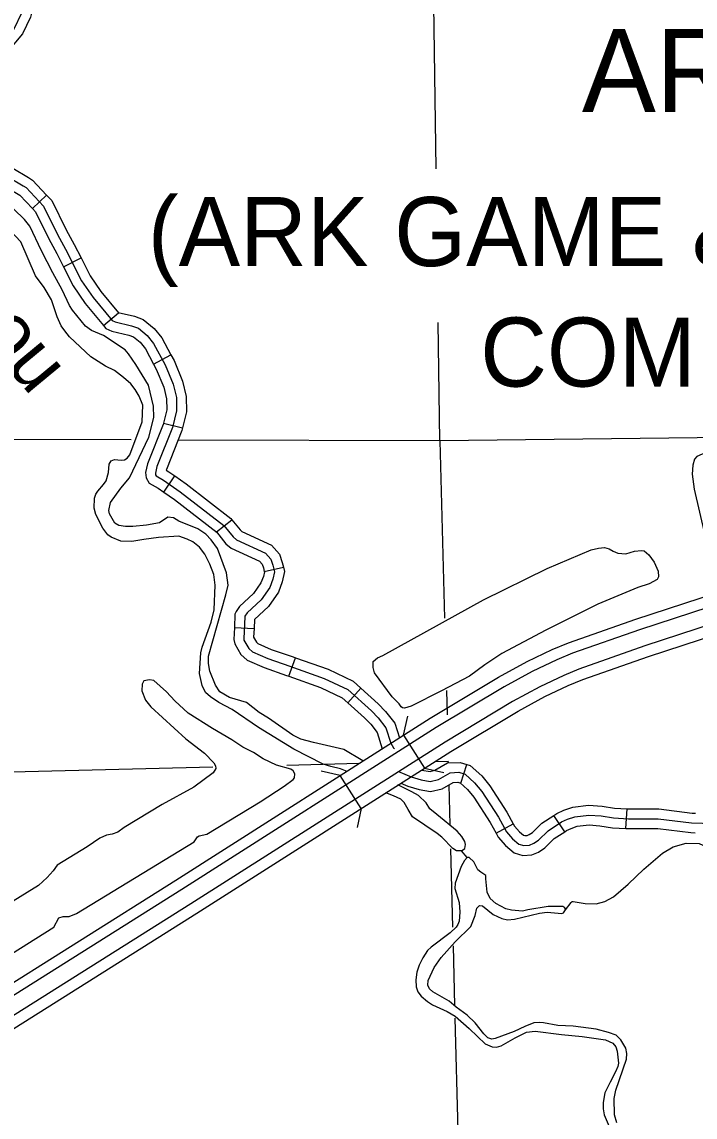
# Model space of a CAD drawing. Extents: x 1084508 to 1142749, y 1057638 to 1093403.
# Drawn here: x 1090132 to 1091747, y 1070432 to 1073059 of the extents above; entities that cross this region are included whole.
import ezdxf

# ---------------------------------------------------------------- set-up
doc = ezdxf.new("R2010")
doc.units = 0
for name, color, linetype in [('Level 19', 7, 'Continuous'), ('Level 32', 7, 'Continuous'), ('Level 35', 7, 'Continuous'), ('Level 39', 7, 'Continuous'), ('Level 5', 7, 'Continuous'), ('Level 7', 7, 'Continuous')]:
    doc.layers.add(name, color=color, linetype=linetype)

msp = doc.modelspace()

# ---------------------------------------------------------------- linework, layer by layer
at = {"layer": 'Level 19'}
for points in [[(1086828.8, 1069564.8), (1086958.3, 1069597.9), (1087305.2, 1069683.8), (1087445.9, 1069710.7), (1087821, 1069773.1), (1088253.5, 1069840.9), (1088436.6, 1069876.1), (1088626, 1069927.2), (1088752.5, 1069969), (1088851.8, 1070006.5), (1088959.6, 1070052.9), (1089051.3, 1070099.1), (1089145.7, 1070149.3), (1089264, 1070224), (1089345.2, 1070271.9), (1090501.3, 1071000.2), (1091111.9, 1071388.7), (1091276, 1071487.3), (1091344.3, 1071524.2), (1091404.7, 1071552.9), (1091443.8, 1071569.2), (1091605.2, 1071625.7), (1092224.5, 1071828.5), (1094022, 1072425.4)], [(1094030.9, 1072400.2), (1092232.9, 1071803.1), (1091613.8, 1071600.4), (1091453.4, 1071544.3), (1091415.6, 1071528.5), (1091356.3, 1071500.4), (1091289.2, 1071464.1), (1091126, 1071366), (1090515.6, 1070977.7), (1089359.1, 1070249.2), (1089277.9, 1070201.2), (1089159.1, 1070126.2), (1089063.6, 1070075.4), (1088970.9, 1070028.7), (1088861.8, 1069981.8), (1088761.4, 1069943.9), (1088633.7, 1069901.6), (1088442.6, 1069850.1), (1088258.1, 1069814.7), (1087825.3, 1069746.7), (1087450.6, 1069684.4), (1087310.9, 1069657.7), (1086964.9, 1069572), (1086833.1, 1069538.3)], [(1094044.5, 1072361.7), (1092245.7, 1071764.4), (1091626.8, 1071561.8), (1091468, 1071506.2), (1091432.2, 1071491.3), (1091374.8, 1071464), (1091309.5, 1071428.7), (1091147.4, 1071331.3), (1090537.4, 1070943.2), (1089380.4, 1070214.3), (1089299.2, 1070166.4), (1089179.6, 1070090.9), (1089082.3, 1070039.1), (1088988.1, 1069991.7), (1088877.1, 1069943.9), (1088775, 1069905.4), (1088645.4, 1069862.5), (1088451.8, 1069810.3), (1088265.1, 1069774.4), (1087831.8, 1069706.5), (1087457.7, 1069644.3), (1087319.6, 1069617.8), (1086974.8, 1069532.5), (1086844.1, 1069499)], [(1086853, 1069473.8), (1086981.3, 1069506.6), (1087325.3, 1069591.8), (1087462.4, 1069618), (1087836, 1069680.1), (1088269.7, 1069748.2), (1088457.8, 1069784.3), (1088653.1, 1069837), (1088783.9, 1069880.3), (1088887.1, 1069919.2), (1088999.4, 1069967.5), (1089094.6, 1070015.5), (1089193, 1070067.8), (1089313.1, 1070143.6), (1089394.3, 1070191.5), (1090551.7, 1070920.7), (1091161.5, 1071308.6), (1091322.7, 1071405.5), (1091386.9, 1071440.2), (1091443.1, 1071466.9), (1091477.6, 1071481.3), (1091635.4, 1071536.5), (1092254, 1071739), (1094053.4, 1072336.6)]]:
    msp.add_lwpolyline(points, dxfattribs=at)
at = {"layer": 'Level 32'}
for p, q in [((1090157.5, 1072611), (1090191.7, 1072643.4)), ((1090232.2, 1072471.4), (1090274.3, 1072492.5)), ((1090328.1, 1072330.6), (1090364.3, 1072360.6)), ((1090448.3, 1072237.8), (1090489.9, 1072260)), ((1090471.9, 1072096.2), (1090517.6, 1072085.1)), ((1090472.6, 1071930.9), (1090499.4, 1071969.5)), ((1090599.5, 1071835.2), (1090636.3, 1071864.6)), ((1090713.7, 1071740.1), (1090759.5, 1071751.1)), ((1090642.1, 1071605.7), (1090689.1, 1071603.6)), ((1090772.5, 1071489.2), (1090788.3, 1071533.6)), ((1090914.1, 1071425.5), (1090945.6, 1071460.5)), ((1091185.2, 1071232.8), (1091199.3, 1071277.7)), ((1091581.3, 1071123.9), (1091584, 1071171)), ((1091434.4, 1071116.2), (1091408.1, 1071155.3)), ((1091269.8, 1071112.5), (1091311, 1071135.2))]:
    msp.add_line(p, q, dxfattribs=at)
for points in [[(1090156.6, 1073133.5), (1090159.5, 1073121.6), (1090160.4, 1073098.9), (1090152.9, 1073069.9), (1090134, 1073030.3), (1090096.4, 1072985.1), (1090086.4, 1072970.3)], [(1090130.7, 1073078), (1090114, 1073043.1), (1090077.6, 1072999.3), (1090062.9, 1072977.5), (1090050.2, 1072964.1), (1089963, 1072900), (1089959.3, 1072895.6), (1089958.6, 1072893.5), (1089959.2, 1072889.9), (1090031.9, 1072734.5), (1090045.1, 1072720.5), (1090059.2, 1072710.5), (1090135.7, 1072665.8)], [(1090058.9, 1072740.2), (1090060.6, 1072738.4), (1090072, 1072730.4), (1090148.4, 1072685.7), (1090157.8, 1072679.2), (1090191.7, 1072643.4)], [(1090024.7, 1072707.9), (1090029.6, 1072702.6), (1090046.5, 1072690.7), (1090123.1, 1072646), (1090127, 1072643.3), (1090157.5, 1072611)], [(1090135.7, 1072665.8), (1090142.4, 1072661.3), (1090184.4, 1072616.9), (1090218, 1072549.1), (1090237.2, 1072514), (1090275.4, 1072437.7), (1090303.1, 1072397.7), (1090348.6, 1072342.6), (1090355.7, 1072339.4), (1090395.5, 1072330), (1090411.7, 1072324.2), (1090432.9, 1072306.9), (1090448.4, 1072287.7), (1090475.9, 1072236.1), (1090495.4, 1072189.9), (1090502.8, 1072157.8), (1090503.3, 1072125.9), (1090493.6, 1072085.8), (1090456.2, 1071992.2), (1090452.9, 1071976.3), (1090453.2, 1071972.6), (1090454.8, 1071970), (1090472.1, 1071959.8), (1090512.3, 1071931.9), (1090617.1, 1071850.8), (1090638.8, 1071823.6), (1090647.2, 1071816.6), (1090716.8, 1071784.5), (1090729.2, 1071769.9), (1090734.2, 1071755.6)], [(1090191.7, 1072643.4), (1090203.9, 1072630.5), (1090238.9, 1072560), (1090258.1, 1072524.9), (1090274.3, 1072492.5)], [(1090157.5, 1072611), (1090164.9, 1072603.3), (1090197.2, 1072538.2), (1090216.4, 1072503.1), (1090232.2, 1072471.4)], [(1090274.3, 1072492.5), (1090295.7, 1072449.7), (1090321.9, 1072411.9), (1090364.3, 1072360.6)], [(1090232.2, 1072471.4), (1090255.1, 1072425.7), (1090284.3, 1072383.4), (1090328.1, 1072330.6)], [(1090363.3, 1072361.8), (1090363.3, 1072361.8), (1090402.2, 1072352.6), (1090423.4, 1072345), (1090449.7, 1072323.5), (1090468.1, 1072300.7), (1090489.9, 1072260)], [(1090328.1, 1072330.6), (1090334, 1072323.4), (1090348, 1072317.1), (1090388.8, 1072307.3), (1090399.9, 1072303.4), (1090416.1, 1072290.2), (1090428.6, 1072274.6), (1090448.3, 1072237.8)], [(1090489.9, 1072260), (1090497.2, 1072246.3), (1090517.9, 1072197.2), (1090526.3, 1072160.6), (1090526.9, 1072123.2), (1090517.6, 1072085.1)], [(1090448.3, 1072237.8), (1090454.7, 1072226), (1090472.9, 1072182.7), (1090479.3, 1072154.9), (1090479.7, 1072128.5), (1090471.9, 1072096.2)], [(1090471.9, 1072096.2), (1090471.1, 1072093), (1090433.6, 1071999), (1090429.1, 1071977.8), (1090430.3, 1071964.9), (1090437.9, 1071952.7), (1090459.4, 1071940), (1090472.6, 1071930.9)], [(1090517.6, 1072085.1), (1090516, 1072078.6), (1090478.9, 1071985.3), (1090478.5, 1071983.4), (1090484.9, 1071979.7), (1090499.4, 1071969.5)], [(1090499.4, 1071969.5), (1090526.3, 1071950.9), (1090633.8, 1071867.7), (1090636.3, 1071864.6)], [(1090472.6, 1071930.9), (1090498.4, 1071912.9), (1090600.5, 1071833.9), (1090599.4, 1071835.2)], [(1090636.3, 1071864.6), (1090655.7, 1071840.2), (1090659.9, 1071836.7), (1090731.3, 1071803.7), (1090749.9, 1071781.9), (1090756.8, 1071762.3), (1090759.5, 1071751.1)], [(1090599.5, 1071835.2), (1090621.9, 1071807.1), (1090634.6, 1071796.6), (1090702.2, 1071765.2), (1090708.5, 1071757.9), (1090711.6, 1071748.9), (1090713.7, 1071740.1)], [(1090734.2, 1071755.6), (1090738, 1071739.9), (1090734.1, 1071721.9), (1090726.8, 1071702.2), (1090705.9, 1071672.2), (1090672.6, 1071641), (1090666.9, 1071632.9), (1090666.8, 1071632.7), (1090664.5, 1071578.8), (1090665.1, 1071575.4), (1090676.4, 1071555.9), (1090685.7, 1071547.7), (1090722, 1071531.6), (1090775.1, 1071513.3), (1090857.7, 1071484), (1090913.9, 1071457.3), (1090970.8, 1071406.2), (1090986.8, 1071389.3), (1091005.7, 1071365.5), (1091017.3, 1071328.2), (1091023.7, 1071317.4), (1091025.9, 1071315.5)], [(1090759.5, 1071751.1), (1090762.1, 1071740.2), (1090756.8, 1071715.3), (1090747.8, 1071691.2), (1090723.8, 1071656.7), (1090690.4, 1071625.4), (1090690.1, 1071624.9), (1090689.1, 1071603.6)], [(1090713.7, 1071740.1), (1090713.9, 1071739.6), (1090711.5, 1071728.5), (1090705.8, 1071713.2), (1090688, 1071687.6), (1090654.7, 1071656.5), (1090646.1, 1071644.2), (1090643.5, 1071637.8), (1090642.1, 1071605.7)], [(1090642.1, 1071605.7), (1090640.8, 1071577), (1090642.8, 1071567), (1090657.9, 1071540.9), (1090672.8, 1071527.6), (1090713.3, 1071509.7), (1090767.3, 1071491.1), (1090772.5, 1071489.2)], [(1090689.1, 1071603.6), (1090688.2, 1071582.5), (1090694.8, 1071571), (1090698.6, 1071567.7), (1090730.6, 1071553.6), (1090782.9, 1071535.5), (1090788.3, 1071533.6)], [(1090788.3, 1071533.6), (1090866.7, 1071505.8), (1090927.1, 1071477.1), (1090945.6, 1071460.5)], [(1090772.5, 1071489.2), (1090848.7, 1071462.2), (1090900.8, 1071437.5), (1090914.1, 1071425.5)], [(1090945.6, 1071460.5), (1090987.2, 1071423.1), (1091004.6, 1071404.8), (1091026.9, 1071376.7), (1091037.8, 1071341.5)], [(1090914.1, 1071425.5), (1090954.3, 1071389.3), (1090969, 1071373.8), (1090984.5, 1071354.3), (1090996.6, 1071315.3)], [(1091091.7, 1071264.2), (1091111.3, 1071260.9), (1091122.9, 1071263.5), (1091152.9, 1071281), (1091183.8, 1071282.5), (1091199.3, 1071277.7)], [(1091199.3, 1071277.7), (1091207.6, 1071275.1), (1091235.3, 1071250.1), (1091254.5, 1071226.5), (1091295.8, 1071162.8), (1091311, 1071135.2)], [(1091035.9, 1071260.3), (1091065.8, 1071247.5), (1091090.2, 1071240.6), (1091112, 1071237), (1091131.6, 1071241.3), (1091159.8, 1071257.8), (1091180.8, 1071258.8), (1091195.7, 1071254.2), (1091218.2, 1071233.8), (1091235.4, 1071212.6)], [(1091041.6, 1071232.3), (1091058, 1071225.2), (1091085.1, 1071217.6), (1091112.6, 1071213), (1091140.3, 1071219.2), (1091166.7, 1071234.6), (1091177.7, 1071235.1), (1091185.2, 1071232.8)], [(1091183.7, 1071233.2), (1091201, 1071217.6), (1091216.4, 1071198.7), (1091255.4, 1071138.5), (1091269.8, 1071112.5)], [(1091235.4, 1071212.6), (1091275.6, 1071150.7), (1091294.6, 1071116.2), (1091309.1, 1071099.4), (1091324.3, 1071086.5), (1091336.7, 1071082.9), (1091349.8, 1071084.1), (1091360.3, 1071088.3), (1091371.6, 1071095.9), (1091394.6, 1071117.9), (1091427, 1071139.6), (1091440.8, 1071146.1), (1091459.1, 1071152.2), (1091492.2, 1071156), (1091521.7, 1071154), (1091551.7, 1071149.2), (1091587.5, 1071147.2), (1091659, 1071147.1), (1091738.6, 1071137.4), (1091816.8, 1071135.4), (1091868.3, 1071131.8), (1091930.3, 1071133.6)], [(1091408.1, 1071155.3), (1091415.3, 1071160.2), (1091432.1, 1071168), (1091454, 1071175.3), (1091491.6, 1071179.6), (1091524.4, 1071177.4), (1091554.2, 1071172.7), (1091584, 1071171)], [(1091584, 1071171), (1091588.2, 1071170.7), (1091660.4, 1071170.7), (1091740.4, 1071160.9), (1091748.4, 1071160.7)], [(1091311, 1071135.2), (1091314.1, 1071129.7), (1091325.7, 1071116.2), (1091335.7, 1071107.7), (1091339, 1071106.8), (1091344.3, 1071107.2), (1091349.2, 1071109.2), (1091356.8, 1071114.3), (1091379.8, 1071136.3), (1091408.1, 1071155.3)], [(1091269.8, 1071112.5), (1091275.2, 1071102.7), (1091292.5, 1071082.7), (1091312.9, 1071065.3), (1091334.3, 1071059.1), (1091355.3, 1071060.9), (1091371.4, 1071067.3), (1091386.5, 1071077.6), (1091409.4, 1071099.5), (1091434.4, 1071116.2)], [(1091434.4, 1071116.2), (1091438.6, 1071119.1), (1091449.6, 1071124.2), (1091464.2, 1071129.1), (1091492.7, 1071132.4), (1091519, 1071130.6), (1091549.1, 1071125.8), (1091581.3, 1071123.9)], [(1091581.3, 1071123.9), (1091586.8, 1071123.6), (1091657.5, 1071123.6), (1091736.9, 1071113.9), (1091747.2, 1071113.6)]]:
    msp.add_lwpolyline(points, dxfattribs=at)
at = {"layer": 'Level 35'}
for points in [[(1090354.4, 1072222.6), (1090333, 1072232.9), (1090297.5, 1072255.3), (1090246.8, 1072303.6), (1090235.1, 1072317.4), (1090226.8, 1072329.7), (1090216.7, 1072351.1), (1090203.5, 1072391.8), (1090186, 1072421.4), (1090165, 1072449.7), (1090129.5, 1072531.2), (1090090.8, 1072573), (1090060.9, 1072597.2), (1090030.8, 1072618.8), (1089996.4, 1072636.6), (1089986.7, 1072645.1)], [(1090206.5, 1072456.7), (1090179.7, 1072509.6), (1090151.5, 1072568.7), (1090138.4, 1072585.2), (1090112.9, 1072609.6), (1090078.3, 1072640.2), (1090072, 1072643.4)], [(1090949.8, 1071286.3), (1090904.4, 1071313), (1090831.5, 1071330.1), (1090801.1, 1071338.3), (1090782, 1071348), (1090723.6, 1071388.9), (1090701.3, 1071402.3), (1090671.4, 1071426.4), (1090630.6, 1071438.3), (1090606.9, 1071451.7), (1090596.7, 1071468), (1090582.8, 1071501.2), (1090580.3, 1071519.7), (1090580, 1071537.6), (1090621.7, 1071684.8), (1090626.9, 1071708), (1090623.5, 1071737.4), (1090601.9, 1071795.2), (1090586.5, 1071816.4), (1090573.8, 1071830.1), (1090554.6, 1071842.4), (1090508.9, 1071861), (1090496.1, 1071869.4), (1090482.2, 1071871.1), (1090462.6, 1071857), (1090431.1, 1071851.5), (1090398.7, 1071848.3), (1090381.1, 1071848), (1090364.7, 1071850.9), (1090355.5, 1071856.6), (1090342.2, 1071878.5), (1090341, 1071886.9), (1090344.5, 1071905.6), (1090370, 1071940.4), (1090390.5, 1071965.3), (1090437.2, 1072062.4), (1090449.2, 1072109.6), (1090448.3, 1072137.3), (1090436.3, 1072187.2), (1090405.6, 1072236.8), (1090388.2, 1072262.3), (1090379.7, 1072272.1), (1090328.2, 1072306.6), (1090299.3, 1072318.5), (1090284.8, 1072329.1), (1090254.1, 1072367.1), (1090246.9, 1072378.5), (1090228.8, 1072415.9), (1090206.5, 1072456.7)], [(1090912.3, 1071260.4), (1090896.7, 1071267.2), (1090873.4, 1071272.4), (1090855.4, 1071278.4), (1090784.7, 1071313.8), (1090699.6, 1071366.4), (1090636.5, 1071409), (1090604.6, 1071426.5), (1090584.4, 1071439.9), (1090573.1, 1071450), (1090564.5, 1071466.6), (1090558.5, 1071495.7), (1090561.9, 1071545.5), (1090564.6, 1071559.1), (1090586.5, 1071618.9), (1090593.7, 1071648.7), (1090595.6, 1071707.6), (1090592.6, 1071732.9), (1090583.3, 1071758.1), (1090571, 1071781.6), (1090558.5, 1071798.8), (1090542.7, 1071811.2), (1090529.1, 1071818), (1090508.4, 1071825.5), (1090460, 1071821.7), (1090424.7, 1071817.4), (1090396.4, 1071812), (1090370, 1071813.1), (1090346.8, 1071822.4), (1090338.5, 1071828.4), (1090326.4, 1071844), (1090310, 1071876.8), (1090306, 1071892.4), (1090306.5, 1071916.3), (1090309.7, 1071925.9), (1090314.5, 1071933.2), (1090328.4, 1071948.8), (1090334.3, 1071957.8), (1090340, 1071977.5), (1090341.5, 1071997.6), (1090346.6, 1072005.7), (1090354.6, 1072008.8), (1090370.7, 1072007.1), (1090378.5, 1072008.6), (1090384.6, 1072011.9), (1090391.3, 1072020), (1090420.7, 1072099.6), (1090422.2, 1072139.6), (1090413.7, 1072161.3), (1090404.1, 1072177.3), (1090393.3, 1072190.8), (1090376.2, 1072206), (1090354.4, 1072222.6)], [(1091985.3, 1072060.6), (1091977, 1072077), (1091971.5, 1072080.9), (1091957.1, 1072081.7), (1091827.3, 1072034.7), (1091798.4, 1072026.5), (1091763.8, 1072021.9), (1091751.4, 1072016.5), (1091746, 1072010), (1091742.1, 1071995.4), (1091740.5, 1071974), (1091744.8, 1071938.3), (1091783.1, 1071772.3), (1091786.5, 1071751.6), (1091794.1, 1071741.8), (1091802.3, 1071739.6), (1092018, 1071803.5), (1092043, 1071816), (1092052.2, 1071823.8), (1092053.6, 1071837.1), (1092050.8, 1071855.9)], [(1090978.1, 1071497.5), (1090974.9, 1071510.3), (1090974.8, 1071524.5), (1090985.7, 1071533.6), (1090998.4, 1071539.1), (1091239.8, 1071672.8), (1091392.5, 1071747.2), (1091497.6, 1071792.2), (1091515.7, 1071796.6), (1091529.7, 1071797.6), (1091540.8, 1071794.9), (1091550.4, 1071788.9), (1091562.1, 1071784.2), (1091580.7, 1071782.7), (1091601.5, 1071789.3), (1091618.3, 1071791.1), (1091625.3, 1071790.1), (1091635.9, 1071780.7), (1091649.3, 1071762.6), (1091658.5, 1071741.5), (1091659.2, 1071728), (1091656.3, 1071721), (1091637.2, 1071710.6), (1091609.9, 1071702.2), (1091514, 1071661.9), (1091388.8, 1071599.3), (1091283.8, 1071543.4), (1091243, 1071516.3), (1091206.2, 1071489.6), (1091139, 1071454.4), (1091065.9, 1071417.7), (1091049.8, 1071412.5), (1091045.4, 1071413), (1091041.9, 1071415.4), (1091037.6, 1071422.8), (1091020.4, 1071440.1)], [(1091020.4, 1071440.1), (1090978.1, 1071497.5)], [(1090761.8, 1071225.7), (1090782.9, 1071241.1), (1090785.9, 1071245.3), (1090786.9, 1071254.8), (1090782.9, 1071262.5), (1090777.4, 1071266.4), (1090742.9, 1071275.7), (1090710.8, 1071291), (1090687.8, 1071305.9), (1090662.3, 1071319.2), (1090636, 1071336.3), (1090589.7, 1071363.7), (1090530.9, 1071400.5), (1090498.9, 1071430.5), (1090479.4, 1071451.6), (1090448.7, 1071478.9), (1090438.3, 1071480.8), (1090424.6, 1071478.1), (1090420.5, 1071469.8), (1090420.4, 1071454.1), (1090428.9, 1071432), (1090441.4, 1071415.5), (1090525.6, 1071339.3), (1090570.3, 1071304.6), (1090593, 1071281.4), (1090596.7, 1071274), (1090597.2, 1071267.7), (1090590.9, 1071257.2), (1090544.4, 1071223.3), (1090468.9, 1071181.8), (1090378, 1071126.3), (1090362.6, 1071115.4), (1090349, 1071110.6), (1090335.3, 1071108.2), (1090318.9, 1071100.8), (1090289.2, 1071079.7), (1090217, 1071036.1), (1090207.7, 1071022.3), (1090193.2, 1071006.1), (1090171.8, 1070987.5), (1089984.7, 1070871.9)], [(1090704.1, 1071188.2), (1090761.8, 1071225.7)], [(1091186.6, 1071070.4), (1091194.6, 1071076), (1091196.1, 1071085.1), (1091194.7, 1071092.3), (1091188, 1071104.7), (1091176.3, 1071117.5), (1091128, 1071157.1), (1091111.2, 1071171.1), (1091101.7, 1071185.4), (1091084, 1071203.1), (1091067.6, 1071212), (1091034.2, 1071228.4)], [(1091186.6, 1071070.4), (1091174.7, 1071070), (1091165.7, 1071075.7), (1091139.8, 1071102.8), (1091128.5, 1071112.2), (1091069, 1071151.7), (1091059.3, 1071169.6), (1091049.2, 1071186.1), (1091041.1, 1071194.3), (1091024, 1071202.5), (1091005, 1071209.3)], [(1089490.8, 1070435.1), (1090209.2, 1070887.5), (1090220.7, 1070909.9), (1090231, 1070913), (1090246, 1070912.6), (1090263, 1070919.7), (1090545.8, 1071092.2), (1090553.2, 1071103.7), (1090557.9, 1071106.4), (1090576.2, 1071110.2), (1090704.1, 1071188.2)], [(1091668.9, 1071064.8), (1091694.9, 1071079.6), (1091726, 1071088.5), (1091756.7, 1071087.6), (1091773.2, 1071080.3), (1091896.6, 1071035), (1091908.1, 1071029.7), (1091915.2, 1071023), (1091934.6, 1070995), (1091944.4, 1070971.5), (1091954.7, 1070952.6), (1091977.6, 1070931.4), (1091994.8, 1070913.1), (1092008.1, 1070889.6), (1092014.6, 1070864.7), (1092022.8, 1070810.7)], [(1091200.8, 1071054.5), (1091186.6, 1071070.4)], [(1091436.4, 1070928.6), (1091449.8, 1070946.7), (1091452.5, 1070948.7), (1091455.1, 1070949), (1091483.5, 1070943.7), (1091509.5, 1070943), (1091530.9, 1070949), (1091551.2, 1070960.1), (1091586.9, 1070990.5), (1091624.3, 1071026), (1091668.9, 1071064.8)], [(1091233.3, 1071019.4), (1091226.2, 1071024.5), (1091216.5, 1071044), (1091205.5, 1071054), (1091200.8, 1071054.5), (1091193.8, 1071047.4), (1091185.8, 1071032.3), (1091171.4, 1070992.9), (1091170.6, 1070980.3), (1091181.1, 1070946), (1091183.1, 1070922.8), (1091181.6, 1070901.7), (1091178.4, 1070893.4), (1091173.9, 1070887.3), (1091159.3, 1070873.3), (1091114.3, 1070839.5), (1091105.5, 1070831), (1091093.8, 1070813.6), (1091085.3, 1070796.4), (1091079.6, 1070778.9), (1091077, 1070760.9), (1091078.2, 1070744.3), (1091082, 1070731.8), (1091089.9, 1070722), (1091105, 1070709), (1091117.5, 1070700.9), (1091152.8, 1070684.8), (1091171.7, 1070673.7), (1091205.5, 1070644.4), (1091225.5, 1070625.2), (1091243.4, 1070607.5), (1091260.2, 1070599.9), (1091270.6, 1070599.3), (1091282.1, 1070602.5), (1091315.3, 1070621.8), (1091342.4, 1070635), (1091363.7, 1070637.6), (1091426.9, 1070629.6), (1091476.3, 1070624.9), (1091532.6, 1070617), (1091549.5, 1070609.1), (1091557, 1070600.2), (1091560.4, 1070589.3), (1091563.2, 1070560.8), (1091561.6, 1070552.6), (1091556.4, 1070540.1), (1091543.1, 1070515.2), (1091531, 1070489.9), (1091526.5, 1070466.5), (1091526.6, 1070451.1), (1091529.3, 1070436.7), (1091556.4, 1070373.8)], [(1091539.2, 1070634.5), (1091510.2, 1070642.1), (1091455.1, 1070650), (1091417.7, 1070651.6), (1091383.4, 1070658), (1091373.3, 1070658.7), (1091360.2, 1070657.3), (1091338.5, 1070649), (1091313.2, 1070636.6), (1091268, 1070620.3), (1091259.9, 1070618.1), (1091250.4, 1070621.9), (1091240.1, 1070631.3), (1091219.8, 1070658), (1091200.7, 1070676), (1091173.8, 1070695.5), (1091157.4, 1070709.4), (1091117.8, 1070732.3), (1091110, 1070739.6), (1091106.3, 1070747.7), (1091106.9, 1070759.3), (1091120.9, 1070790.6), (1091137.7, 1070814.4), (1091171.9, 1070852), (1091209.3, 1070888.5), (1091219.4, 1070915.5), (1091223.5, 1070933), (1091230.2, 1070939.5), (1091237.1, 1070938.4), (1091262.9, 1070917.3), (1091283.5, 1070907.6), (1091297.4, 1070904.9), (1091314.3, 1070906.4), (1091374, 1070920.9), (1091392.1, 1070923.1), (1091427.9, 1070919.8), (1091431.6, 1070921.2), (1091436.4, 1070928.6), (1091434.4, 1070933.3), (1091430.2, 1070936.6), (1091395.1, 1070937), (1091345.9, 1070928.8), (1091332.8, 1070925.2), (1091306.7, 1070927.8), (1091293.1, 1070931.1), (1091268.9, 1070943.9), (1091256, 1070956.3), (1091248.6, 1070971.2), (1091245.1, 1071003.5), (1091245.1, 1071011.3), (1091233.3, 1071019.4)], [(1091559.4, 1070417.6), (1091554.1, 1070436.9), (1091553.1, 1070476.5), (1091556.8, 1070496.4), (1091582.7, 1070570.2), (1091583.2, 1070584.1), (1091581.2, 1070597.2), (1091569, 1070616.6), (1091557.6, 1070627.9), (1091539.2, 1070634.5)]]:
    msp.add_lwpolyline(points, dxfattribs=at)
at = {"layer": 'Level 39'}
for p, q in [((1091047.7, 1071347.8), (1091058, 1071393.7)), ((1091047.7, 1071347.8), (1091098.3, 1071268.3)), ((1090896, 1071251.3), (1090850, 1071261.5)), ((1090946.5, 1071171.8), (1090896, 1071251.3)), ((1091098.3, 1071268.3), (1091144.2, 1071258.1)), ((1090946.5, 1071171.8), (1090936.3, 1071125.9))]:
    msp.add_line(p, q, dxfattribs=at)
at = {"layer": 'Level 5'}
for points in [[(1091126, 1072706.7), (1091119.7, 1073156.3)], [(1091135.1, 1072054.1), (1091131.1, 1072337.7)], [(1091889.3, 1072062.3), (1091135.1, 1072054.1), (1090506.9, 1072055.8)], [(1090394.4, 1072056.1), (1089447.7, 1072058.6), (1088631, 1072046.8)], [(1091135.1, 1072054.1), (1091146.1, 1071628.7)], [(1091150.7, 1071454.9), (1091152.2, 1071396.5)]]:
    msp.add_lwpolyline(points, dxfattribs=at)
at = {"layer": 'Level 7'}
for points in [[(1090940.2, 1071279.4), (1090768, 1071275.1)], [(1091155.1, 1071284.7), (1091122.7, 1071283.9)], [(1091155.1, 1071284.7), (1091155.2, 1071281.1)], [(1090590, 1071270.7), (1089464, 1071242.7)], [(1091156.6, 1071228.6), (1091159.1, 1071132.7)], [(1091160.6, 1071075), (1091165.5, 1070887.1)], [(1091166.6, 1070842.1), (1091170.4, 1070699.1)], [(1091171.1, 1070669), (1091178.2, 1070398.8), (1091181.4, 1070060.2)]]:
    msp.add_lwpolyline(points, dxfattribs=at)

# ---------------------------------------------------------------- texts
at = {"layer": 'Level 35'}
msp.add_text('Bayou', height=132.58, rotation=309.6109, dxfattribs=at).set_placement((1089834.6, 1072546))
at = {"layer": 'Level 7'}
for s, height, p in [('AREA', 198.88, (1091475.7, 1072842.8)), ('(ARK GAME & FISH', 165.73, (1090434.4, 1072473)), ('COMMISSION)', 165.73, (1091231.8, 1072184))]:
    msp.add_text(s, height=height, dxfattribs=at).set_placement(p)

doc.saveas('drawing.dxf')
